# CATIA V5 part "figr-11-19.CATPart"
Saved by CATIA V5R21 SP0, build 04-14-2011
Part number: Part1
Bounding box of the stored display mesh (mm): x -112.891 to 155.069, y -166 to 177, z -20.381 to 17.354
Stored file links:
  D:\CATIA V5R21 E-RESOURCES\CATIA-V5R21\catia-v5r21-prt\c11-catia-v5r21-prt\c11-catia-v5r21-figr-11-19.CATPart
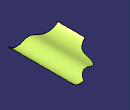
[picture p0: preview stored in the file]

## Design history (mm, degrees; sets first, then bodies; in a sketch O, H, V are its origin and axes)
Set1
  Sketch1 on zx-plane, origin (0, 0, 0), H (-1, 0, 0), V (0, 0, 1)
    spline S1 through (-155.0686, 17.3535) (-88.0787, 0) (-53.6625, 10.5338) (-6.5258, 0) (112.8909, 0)
    point P1 (-88.0787, 0)
    point P2 (-6.5258, 0)
    point P3 (112.8909, 0)
    coincidence: P1 H, P2 H, P3 H
  Extrude1: Element1 Sketch1, Lim1 177, Lim2 166, Direction zx-plane
  Sketch2 on xy-plane, origin (0, 0, 0), H (1, 0, 0), V (0, 1, 0)
    spline S1 through (-167.4699, -22.0252) (-66.0833, 12.4475) (-43.2893, 80.3989) (-11.0164, 123.7609) (37.393, 134.2276) (93.5198, 192.542)
  Extrude2: Element1 Sketch2, Lim1 94, Lim2 109, Direction xy-plane
  Trim1: Element1 Extrude1, Element2 Extrude2
  DatumSurface1
  DatumSurface2
  StUntrimFeature1 "CATStUntrimFeatureName": SpecToUntrim DatumSurface1
Body1 (main body)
